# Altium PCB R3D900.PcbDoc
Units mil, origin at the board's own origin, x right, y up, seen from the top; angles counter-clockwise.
Board outline 3947.04 x 3947.04 mil, 2 copper layers (Top Layer, Bottom Layer); 90 components, 62 nets, 371 pads, 65 vias.
Unrouted connection lines stored in the file: 1.
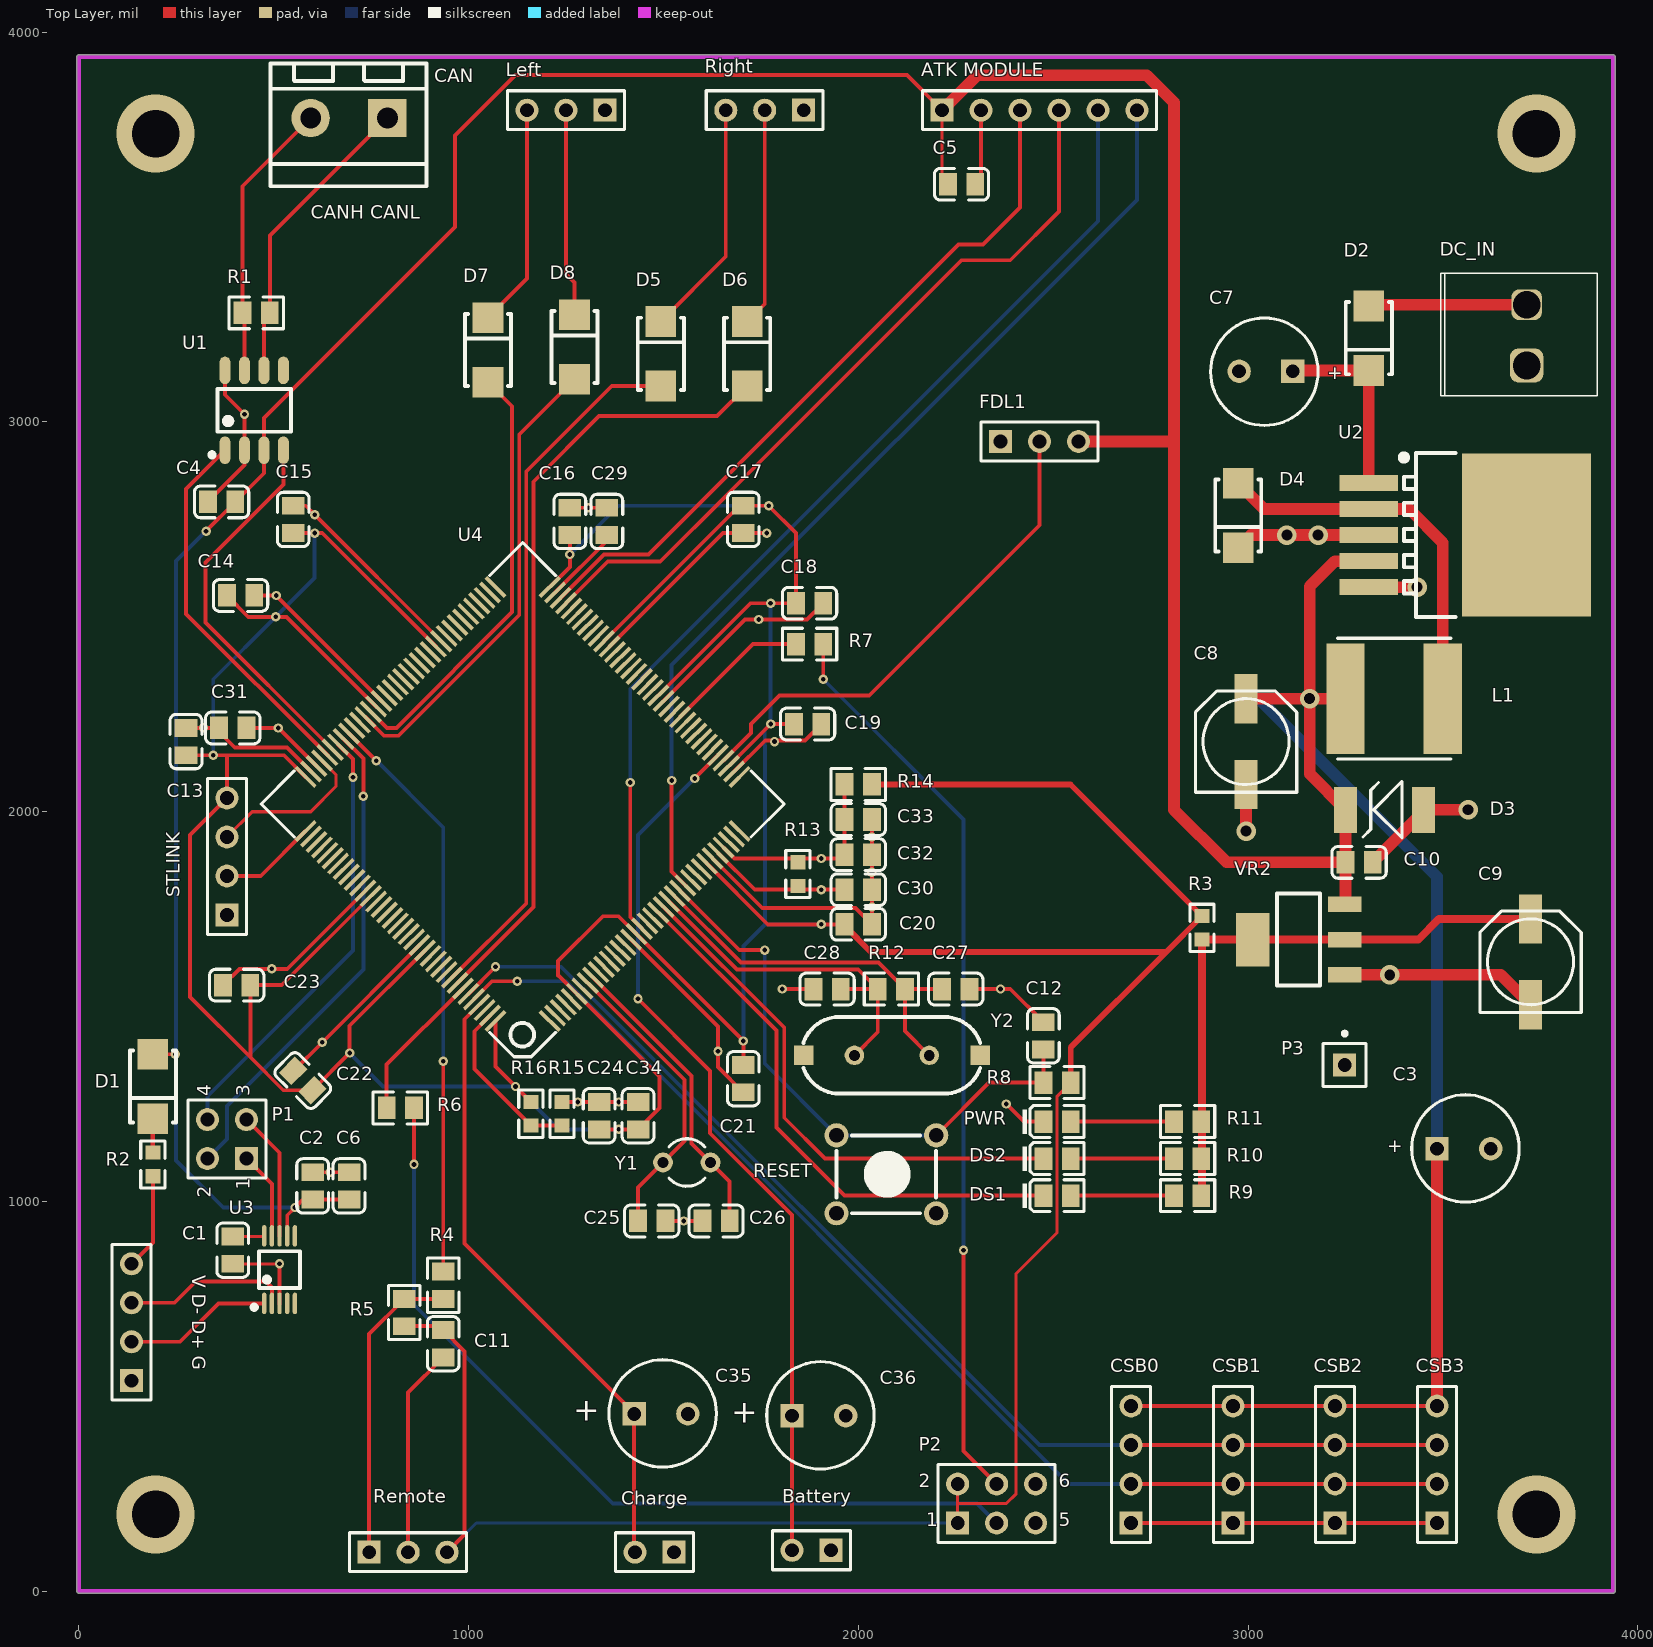
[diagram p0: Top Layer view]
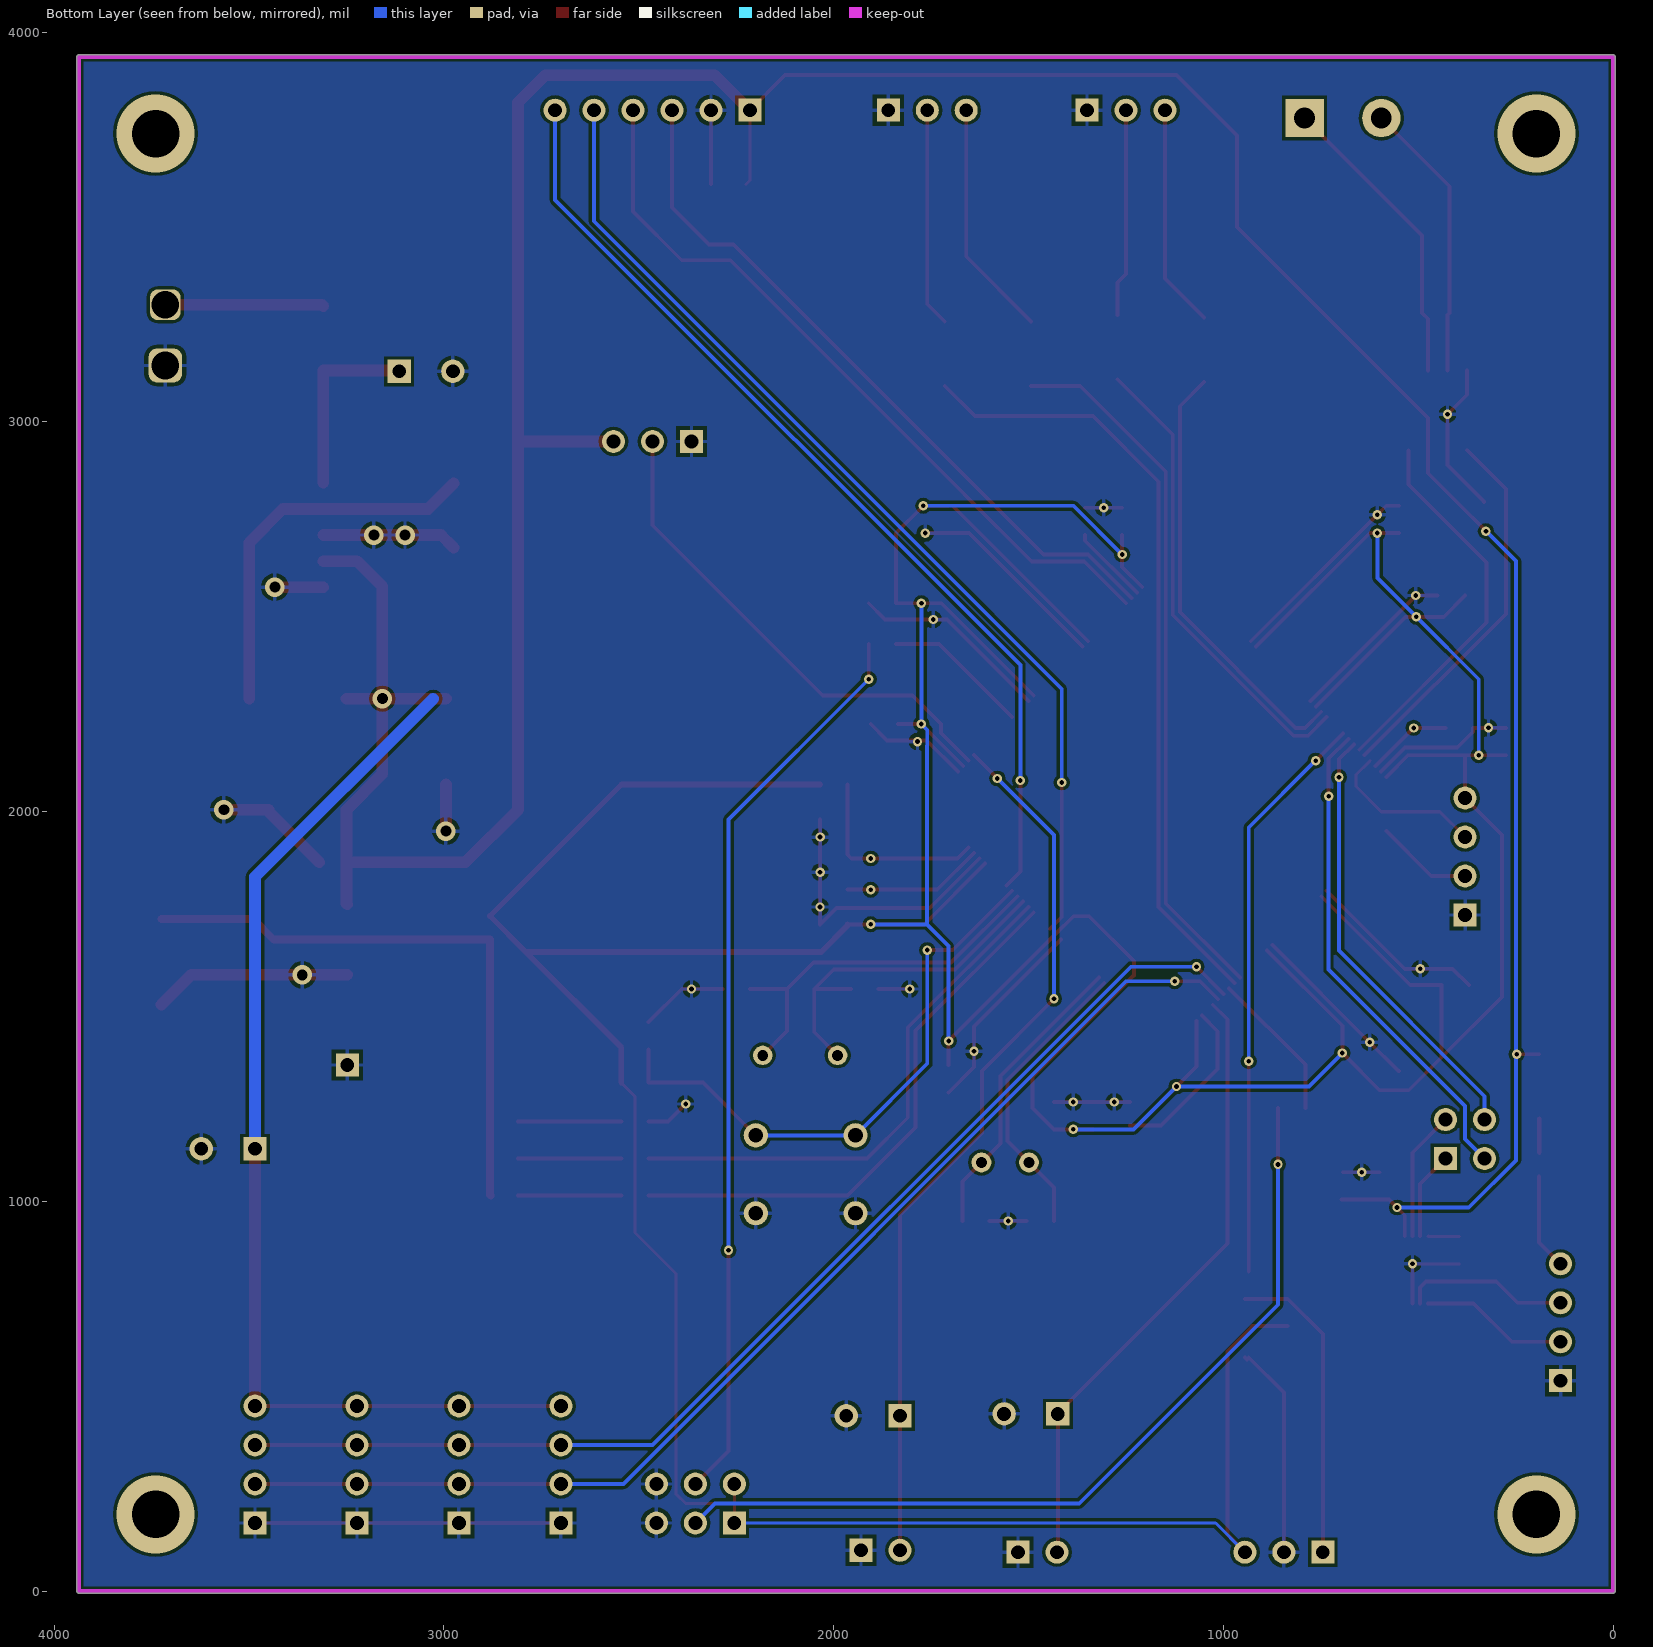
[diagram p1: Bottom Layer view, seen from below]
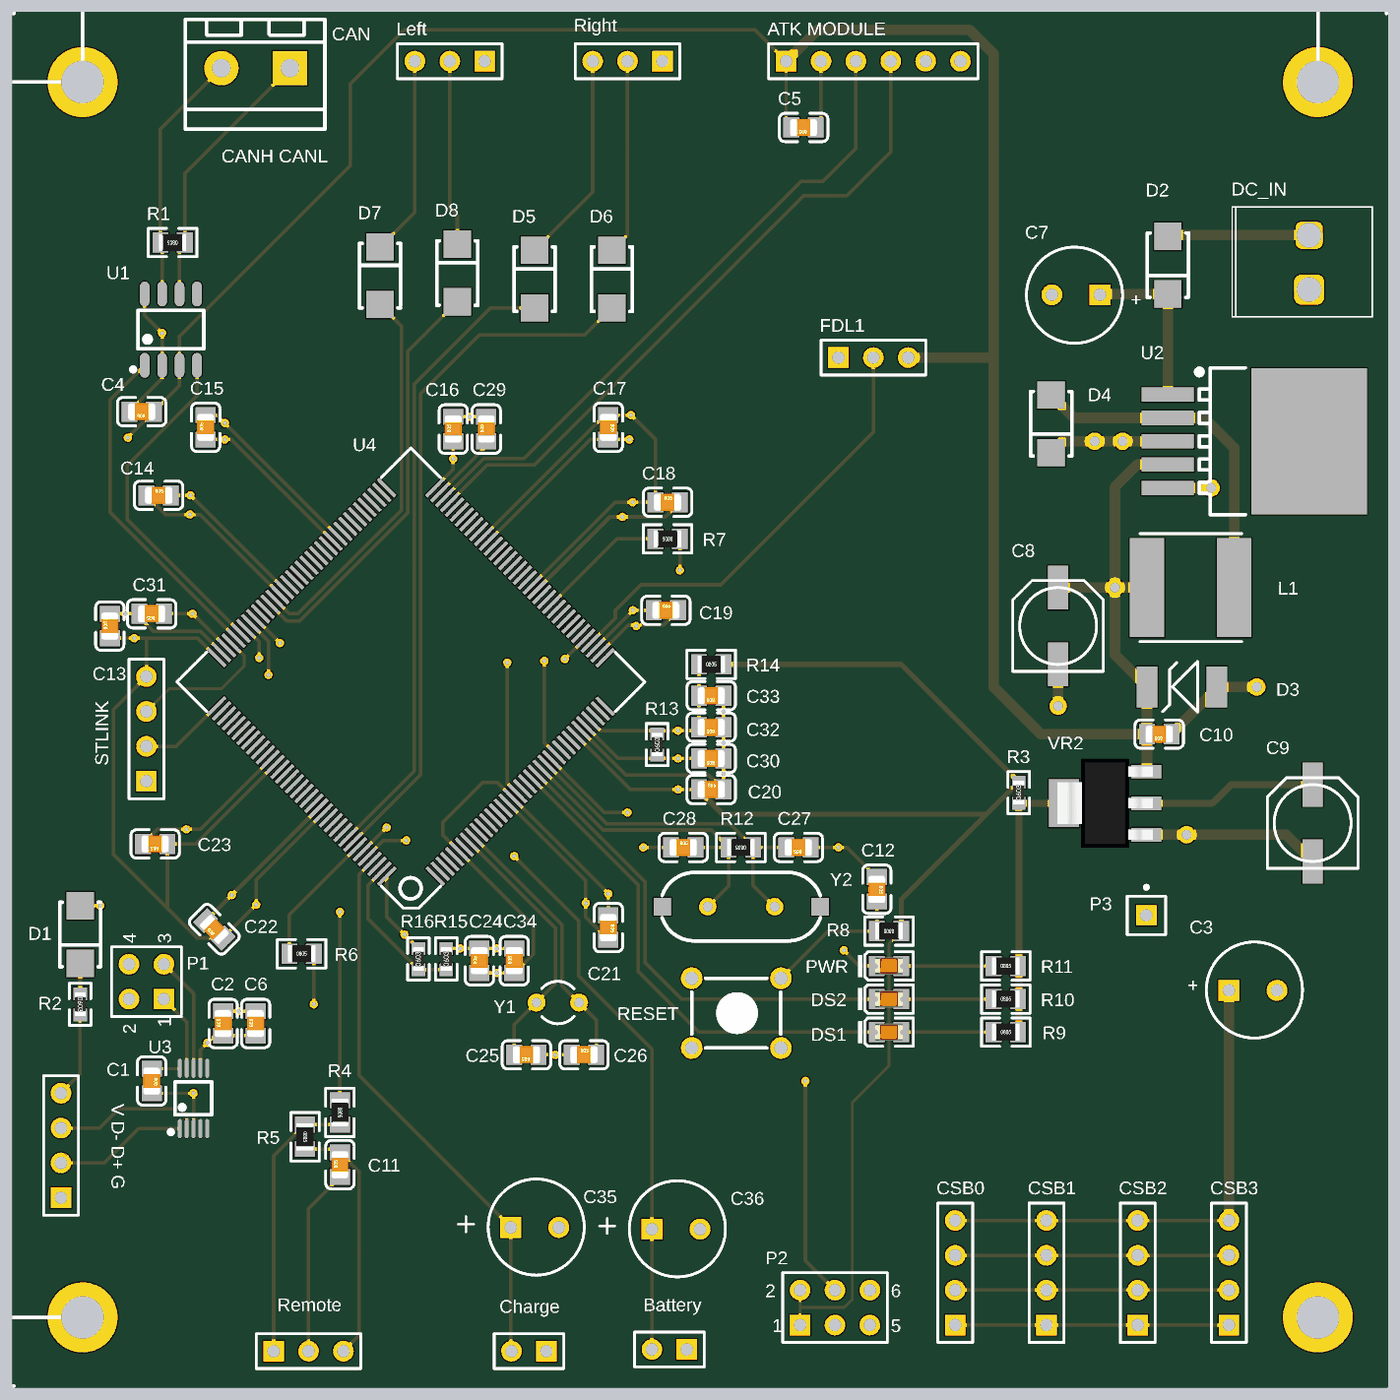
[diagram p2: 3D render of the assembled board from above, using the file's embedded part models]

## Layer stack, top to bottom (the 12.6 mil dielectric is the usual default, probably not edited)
Top Solder: solder mask 0.4, Solder Resist, Dk 3.5
Top Layer: signal copper 1.4
Dielectric 1: dielectric 12.6, FR-4, Dk 4.8
Bottom Layer: signal copper 1.4
Bottom Solder: solder mask 0.4, Solder Resist, Dk 3.5

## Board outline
-5.02,0 ccw(c0,0) 0,-5.02 3937.01,-5.02 ccw(c3937.01,0) 3942.02,0 3942.02,3937.01 ccw(c3937.01,3937.01) 3937.01,3942.02 0,3942.02 ccw(c0,3937.01) -5.02,3937.01

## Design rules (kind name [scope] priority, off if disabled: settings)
Clearance [All] p1: gap=8 ignorepadtopadclearanceinfootprint=TRUE
PolygonConnect [All] p1: connectstyle=Relief reliefconductorwidth=10 reliefentries=4 polygonreliefangle="90 Angle" airgapwidth=10
RoutingVias [All] p1: holewidth=28 width=50 viastyle="Through Hole" minholewidth=28 minwidth=50 maxholewidth=28 maxwidth=50
SolderMaskExpansion [All] p1: expansion=4
Width [All] p1: maxlimit=30 minlimit=8 preferedwidth=10
30 further rules are at their usual default settings.

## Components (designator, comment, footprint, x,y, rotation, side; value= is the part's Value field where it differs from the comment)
"ATK MODULE" "Header 6" HDR1X6 2215,3800 r0 top
Battery "Header 2" HDR1X2 1930,105 r180 top
C1 "100nF(104) 10% 50V" LC-0805_C 395,875 r270 top
C2 "100nF(104) 10% 50V" LC-0805_C 600,1040 r90 top
C3 "Cap" CAP-DIP-3.5 3485,1135 r180 top
C4 "100nF(104) 10% 50V" LC-0805_C 366.42,2795 r180 top
C5 "100nF(104) 10% 50V" LC-0805_C 2265,3610 r180 top
C6 "10uF (106) 10% 25V" LC-0805_C 693.35,1040 r90 top
C7 "Cap" CAP-DIP-3.5 3115,3130 r0 top
C8 "220uF" CC6.56.5 2995,2180 r270 top
C9 "22uF" CC6.56.5 3725,1615 r270 top
C10 "10uF (106) 10% 25V" LC-0805_C 3285,1870 r180 top
C11 "100nF(104) 10% 50V" LC-0805_C 935,634.96 r90 top
C12 "100nF(104) 10% 50V" LC-0805_C 2474.96,1425 r270 top
C13 "100nF(104) 10% 50V" LC-0805_C 275,2180.04 r90 top
C14 "100nF(104) 10% 50V" LC-0805_C 415,2554.92 r0 top
C15 "100nF(104) 10% 50V" LC-0805_C 550,2750 r90 top
C16 "100nF(104) 10% 50V" LC-0805_C 1260,2745 r90 top
C17 "100nF(104) 10% 50V" LC-0805_C 1705,2750 r270 top
C18 "100nF(104) 10% 50V" LC-0805_C 1875,2535 r0 top
C19 "100nF(104) 10% 50V" LC-0805_C 1870,2225 r0 top
C20 "100nF(104) 10% 50V" LC-0805_C 2000,1711.06 r0 top
C21 "100nF(104) 10% 50V" LC-0805_C 1705,1315 r270 top
C22 "100nF(104) 10% 50V" LC-0805_C 574.78,1310.22 r135 top
C23 "100nF(104) 10% 50V" LC-0805_C 405,1555 r180 top
C24 "100nF(104) 10% 50V" LC-0805_C 1335,1220 r90 top
C25 "1.0pF (010) 0.25pF 50V" LC-0805_C 1469.96,950 r180 top
C26 "1.0pF (010) 0.25pF 50V" LC-0805_C 1635,950 r0 top
C27 "22pF (220) 5% 50V" LC-0805_C 2250,1545 r180 top
C28 "22pF (220) 5% 50V" LC-0805_C 1919.96,1545 r0 top
C29 "2.2uF (225) 20% 50V" LC-0805_C 1355,2745 r90 top
C30 "2.2uF (225) 20% 50V" LC-0805_C 2000,1800 r180 top
C31 "2.2uF (225) 20% 50V" LC-0805_C 395,2215 r180 top
C32 "10uF (106) 10% 25V" LC-0805_C 2000,1890 r180 top
C33 "100nF(104) 10% 50V" LC-0805_C 2000,1980 r180 top
C34 "100nF(104) 10% 50V" LC-0805_C 1435,1220 r90 top
C35 "Cap" CAP-DIP-3.5 1425,455 r180 top
C36 "Cap" CAP-DIP-3.5 1830,450 r180 top
CAN "CAN" HEAD2L-0.8 791.85,3780 r180 top
Charge "Header 2" HDR1X2 1527.2,100 r180 top
CSB0 "Header 4" HDR1X4 2700,175 r90 top
CSB1 "Header 4" HDR1X4 2961.67,175 r90 top
CSB2 "Header 4" HDR1X4 3223.33,175 r90 top
CSB3 "Header 4" HDR1X4 3485,175 r90 top
D1 "SS210" LC-SMA(DO-214AC)_S1 190,1295 r90 top
D2 "SS210" LC-SMA(DO-214AC)_S1 3310,3215 r90 top
D3 "SMBJ5.0A" SMBJ 3355,2005 r180 top
D4 "SS54" LC-SMA(DO-214AC)_S1 2975,2760 r90 top
D5 "SS210" LC-SMA(DO-214AC)_S1 1493.33,3175 r270 top
D6 "SS210" LC-SMA(DO-214AC)_S1 1715,3175 r270 top
D7 "SS210" LC-SMA(DO-214AC)_S1 1050,3185 r270 top
D8 "SS210" LC-SMA(DO-214AC)_S1 1271.67,3192.32 r270 top
DC_IN "Header 2" "VH-2A - Circle Hole" 3715,3145 r90 top
DS1 "红灯 0805" LC-0805_LED_S1 2510,1015 r0 top
DS2 "翠绿 0805" LC-0805_LED_S1 2510,1110 r0 top
FDL1 "Header 3" HDR1X3 2365,2950 r0 top
L1 "33uH" L_SOP74 3250,2290 r0 top
Left "Header 3" HDR1X3 1350,3800 r180 top
P1 "Header 2X2" HDR2X2 430,1110 r90 top
P2 "Header 3X2" HDR2X3 2255,175 r0 top
P3 "Plug" PIN1 3248.11,1350.04 r0 top
PWR "蓝灯 0805" LC-0805_LED_S1 2510,1205 r0 top
R1 "120Ω (1200) ±1%" LC-0805_R 455,3280 r180 top
R2 "1Ω (1R00) ±1%" LC-0603_R 190,1095 r270 top
R3 "0Ω (0R0) ±1%" LC-0603_R 2882.18,1702.18 r90 top
R4 "1KΩ (1001) ±1%" LC-0805_R 935,784.96 r270 top
R5 "4.7KΩ (4701) ±1%" LC-0805_R 835,714.96 r270 top
R6 "10KΩ (1002) ±1%" LC-0805_R 825,1239.88 r0 top
R7 "10KΩ (1002) ±1%" LC-0805_R 1875,2430 r180 top
R8 "10KΩ (1002) ±1%" LC-0805_R 2510,1305 r180 top
R9 "510KΩ (5103) ±1%" LC-0805_R 2845,1015 r0 top
R10 "510KΩ (5103) ±1%" LC-0805_R 2845,1110 r0 top
R11 "510KΩ (5103) ±1%" LC-0805_R 2845,1205 r0 top
R12 "1MΩ (1004) ±1%" LC-0805_R 2085,1545 r180 top
R13 "0Ω (0R0) ±1%" LC-0603_R 1845,1840 r90 top
R14 "10Ω (10R0) ±1%" LC-0805_R 2000,2070 r0 top
R15 "0Ω (0R0) ±1%" LC-0603_R 1240,1225 r90 top
R16 "0Ω (0R0) ±1%" LC-0603_R 1160,1225 r90 top
Remote "Header 3" HDR1X3 745,100 r0 top
RESET "KEY_M" KEY_M 1944.09,1169.69 r0 top
Right "Header 3" HDR1X3 1860,3800 r180 top
STLINK "Header 4" HDR1X4 380,1735 r90 top
U1 "CAN/TJA1050T/CM" LC-SOIC-8_150mil 450,3030 r0 top
U2 "LM2596SX-5.0/NOPB" LC-TO-263-5 3309.49,2710 r180 top
U3 "CH340E" LC-MSOP-10 515,825 r0 top
U4 "STM32F407ZET6" LQFP144 1208.14,1463.34 r135 top
"V D- D+ G" "Header 4" HDR1X4 135,540 r90 top (schematic designator "G D+ D- V")
VR2 "AMS1117-3.3" LC-SOT-223 3130,1671.87 r0 top
Y1 "32.768K" R38 1560,1100 r90 top
Y2 "8MHz" XTAL_US 2182.13,1375 r180 top

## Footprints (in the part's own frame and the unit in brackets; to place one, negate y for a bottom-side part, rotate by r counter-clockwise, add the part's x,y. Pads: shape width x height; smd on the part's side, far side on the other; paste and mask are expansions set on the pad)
CAP-DIP-3.5 [mil]
  rect 60x60 hole 35.43: 1(0,0)
  round 60 hole 35.43: 2(-137.8,0)
  silkscreen extent -211,-139 65,137
CC6.56.5 [mm]
  rect 3.2x1.5 smd: 1(-2.794,0) 2(2.8,0)
  silkscreen extent -3.3,-3.3 3.3,3.3
HDR1X2 [mm] "Connector; Header; 2 Position"
  rect 1.5x1.5 hole 0.9: 1(0,0)
  round 1.5 hole 0.9: 2(2.54,0)
  silkscreen extent -1.27,-1.27 3.81,1.27
HDR1X3 [mm] "Connector; Header; 3 Position"
  rect 1.5x1.5 hole 0.9: 1(0,0)
  round 1.5 hole 0.9: 2(2.54,0) 3(5.08,0)
  silkscreen extent -1.27,-1.27 6.35,1.27
HDR1X4 [mm] "Connector; Header; 4 Position"
  rect 1.5x1.5 hole 0.9: 1(0,0)
  round 1.5 hole 0.9: 2(2.54,0) 3(5.08,0) 4(7.62,0)
  silkscreen extent -1.27,-1.27 8.89,1.27
HDR1X6 [mm] "Connector; Header; 6 Position"
  rect 1.5x1.5 hole 0.9: 1(0,0)
  round 1.5 hole 0.9: 2(2.54,0) 3(5.08,0) 4(7.62,0) 5(10.16,0) 6(12.7,0)
  silkscreen extent -1.27,-1.27 13.97,1.27
HDR2X2 [mm] "Connector; Header; 2x2 Position"
  rect 1.5x1.5 hole 0.9: 1(0,0)
  round 1.5 hole 0.9: 2(0,2.54) 3(2.54,0) 4(2.54,2.54)
  silkscreen extent -1.27,-1.27 3.81,3.81
HDR2X3 [mm] "Connector; Header; 3x2 Position"
  rect 1.5x1.5 hole 0.9: 1(0,0)
  round 1.5 hole 0.9: 2(0,2.54) 3(2.54,0) 4(2.54,2.54) 5(5.08,0) 6(5.08,2.54)
  silkscreen extent -1.27,-1.27 6.35,3.81
HEAD2L-0.8 [mm]
  rect 2.5x2.5 hole 1.35: 1(0,0)
  round 2.5 hole 1.35: 2(5,0)
  silkscreen extent -2.54,-3.56 7.62,4.45
KEY_M [mil]
  round 62 hole 38: 1(0,0) 1(255.91,0) 2(0,-200) 2(255.91,-200)
  silkscreen extent 0,-200 255,0
L_SOP74 [mm]
  rect 2.5x7.2 smd: 1(0,0) 2(6.35,0)
  silkscreen extent -0.51,-3.94 6.89,3.94
LC-0603_R [mm]
  rect 0.93x0.98 smd: 1(-0.77,0) 2(0.77,0)
  silkscreen extent -1.53,-0.79 1.54,0.79, body extent -0.85,-0.4 0.85,0.4, height 0.56
LC-0805_C [mm]
  rect 1.16x1.47 smd: 1(-0.89,0) 2(0.89,0)
  silkscreen extent -1.77,-1.04 1.77,1.04, body extent -1,-0.62 1,0.63, height 0.77
LC-0805_LED_S1 [mm]
  rect 1.16x1.47 smd: A(0.89,0) K(-0.89,0)
  silkscreen extent -2.24,-1.04 1.77,1.03, body extent -1.01,-0.62 1.01,0.62, height 1.1
LC-0805_R [mm]
  rect 1.16x1.47 smd: 1(-0.89,0) 2(0.89,0)
  silkscreen extent -1.77,-1.04 1.77,1.03, body extent -1,-0.62 1,0.63, height 0.49
LC-MSOP-10 [mm]
  oval 0.28x1.4 smd mask+0.051: 1(-1,-2.2) 2(-0.5,-2.2) 3(0,-2.2) 4(0.5,-2.2) 5(1,-2.2) 6(1,2.2) 7(0.5,2.2) 8(0,2.2) 9(-0.5,2.2) 10(-1,2.2)
  silkscreen extent -1.8,-2.6 1.33,1.2
LC-SMA(DO-214AC)_S1 [mm]
  rect 2x2 smd: 1(2.1,0) 2(-2.1,0)
  silkscreen extent -2.35,-1.5 2.35,1.5
LC-SOIC-8_150mil [mm]
  oval 0.7x1.8 smd: 1(-1.905,-2.6) 2(-0.635,-2.6) 3(0.635,-2.6) 4(1.905,-2.6) 5(1.905,2.6) 6(0.635,2.6) 7(-0.635,2.6) 8(-1.905,2.6)
  silkscreen extent -2.9,-3.05 2.4,1.4
LC-SOT-223 [mm]
  rect 2.2x1 smd: 1(3,-2.3) 2(3,0) 3(3,2.3)
  rect 2.2x3.5 smd: 2(-3,0)
  silkscreen extent -1.4,-3 1.4,3, body extent -3.49,-3.24 3.49,3.24, height 1.64
LC-TO-263-5 [mm]
  rect 8.4x10.65 smd: 0(-10.3,0)
  rect 3.8x1.05 smd: 1(0,-3.4) 2(0,-1.7) 3(0,0) 4(0,1.7) 5(0,3.4)
  silkscreen extent -5.65,-5.35 -2.1,5.35
LQFP144 [mil]
  rect 70.87x10 smd: 1(-0.35,0.02) 2(-0.35,-19.66) 3(-0.35,-39.35) 4(-0.35,-59.03) 5(-0.35,-78.72) 6(-0.35,-98.4) 7(-0.35,-118.09) 8(-0.35,-137.77) 9(-0.35,-157.46) 10(-0.35,-177.14) 11(-0.35,-196.83) 12(-0.35,-216.51) 13(-0.35,-236.2) 14(-0.35,-255.88) 15(-0.35,-275.57) 16(-0.35,-295.25) 17(-0.35,-314.94) 18(-0.35,-334.62) 19(-0.35,-354.31) 20(-0.35,-373.99) 21(-0.35,-393.68) 22(-0.35,-413.36) 23(-0.35,-433.05) 24(-0.35,-452.73) 25(-0.35,-472.42) 26(-0.35,-492.1) 27(-0.35,-511.79) 28(-0.35,-531.47) 29(-0.35,-551.16) 30(-0.35,-570.84) 31(-0.35,-590.53) 32(-0.35,-610.21) 33(-0.35,-629.9) 34(-0.35,-649.58) 35(-0.35,-669.27) 36(-0.35,-688.95) 73(885.47,-688.95) 74(885.47,-669.27) 75(885.47,-649.58) 76(885.47,-629.9) 77(885.47,-610.21) 78(885.47,-590.53) 79(885.47,-570.84) 80(885.47,-551.16) 81(885.47,-531.47) 82(885.47,-511.79) 83(885.47,-492.1) 84(885.47,-472.42) 85(885.47,-452.73) 86(885.47,-433.05) 87(885.47,-413.36) 88(885.47,-393.68) 89(885.47,-373.99) 90(885.47,-354.31) 91(885.47,-334.62) 92(885.47,-314.94) 93(885.47,-295.25) 94(885.47,-275.57) 95(885.47,-255.88) 96(885.47,-236.2) 97(885.47,-216.51) 98(885.47,-196.83) 99(885.47,-177.14) 100(885.47,-157.46) 101(885.47,-137.77) 102(885.47,-118.09) 103(885.47,-98.4) 104(885.47,-78.72) 105(885.47,-59.03) 106(885.47,-39.35) 107(885.47,-19.66) 108(885.47,0.02)
  rect 10x70.87 smd: 37(98.07,-787.38) 38(117.76,-787.38) 39(137.44,-787.38) 40(157.13,-787.38) 41(176.81,-787.38) 42(196.5,-787.38) 43(216.18,-787.38) 44(235.87,-787.38) 45(255.55,-787.38) 46(275.24,-787.38) 47(294.92,-787.38) 48(314.61,-787.38) 49(334.29,-787.38) 50(353.98,-787.38) 51(373.66,-787.38) 52(393.35,-787.38) 53(413.03,-787.38) 54(432.72,-787.38) 55(452.4,-787.38) 56(472.09,-787.38) 57(491.77,-787.38) 58(511.46,-787.38) 59(531.14,-787.38) 60(550.83,-787.38) 61(570.51,-787.38) 62(590.2,-787.38) 63(609.88,-787.38) 64(629.57,-787.38) 65(649.25,-787.38) 66(668.94,-787.38) 67(688.62,-787.38) 68(708.31,-787.38) 69(727.99,-787.38) 70(747.68,-787.38) 71(767.36,-787.38) 72(787.05,-787.38) 109(787.05,98.45) 110(767.36,98.45) 111(747.68,98.45) 112(727.99,98.45) 113(708.31,98.45) 114(688.62,98.45) 115(668.94,98.45) 116(649.25,98.45) 117(629.57,98.45) 118(609.88,98.45) 119(590.2,98.45) 120(570.51,98.45) 121(550.83,98.45) 122(531.14,98.45) 123(511.46,98.45) 124(491.77,98.45) 125(472.09,98.45) 126(452.4,98.45) 127(432.72,98.45) 128(413.03,98.45) 129(393.35,98.45) 130(373.66,98.45) 131(353.98,98.45) 132(334.29,98.45) 133(314.61,98.45) 134(294.92,98.45) 135(275.24,98.45) 136(255.55,98.45) 137(235.87,98.45) 138(216.18,98.45) 139(196.5,98.45) 140(176.81,98.45) 141(157.13,98.45) 142(137.44,98.45) 143(117.76,98.45) 144(98.07,98.45)
  silkscreen extent -32,-819 917,130
PIN1 [mm] "Connector; Plug"
  rect 1.5x1.5 hole 0.9: 1(0,0)
  silkscreen extent -1.4,-1.4 1.4,2.17
R38 [mm] "Crystal, Thru-Hole; 2 Leads; Body 3.1 x 8.2 mm (Dia.xH)"
  round 1.3 hole 0.7: 1(0,1.55) 2(0,-1.55)
  silkscreen extent -1.55,-1.19 1.55,1.17
SMBJ [mm]
  rect 1.5x3 smd: 1(-2.413,0) 2(2.667,0)
  silkscreen extent -1.02,-1.85 1.52,1.83
"VH-2A - Circle Hole" [mm] "Header 2 use for Power"
  rrect50% 2.2x2.2 hole 1.8: 1(0,0)
  rrect50% 2x2 hole 1.8: 2(3.96,0)
  silkscreen extent -1.98,-4.6 6.02,5.61
XTAL_US [mil]
  round 50 hole 28: 1(0,0) 2(192.13,0)
  rect 50x50 smd: ""(-130.32,0) ""(322.44,0)
  silkscreen extent -131,-98 323,98

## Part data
"ATK MODULE": "Header, 6-Pin"
Battery Charge: "Header, 2-Pin"
C1 C2 C4 C5 C11 C12 C13 C14 C15 C16 C17 C18 C19 C20 C21 C22 C23 C24 C33 C34: library part "0805 100nF(104) 10% 50V", "贴片电容", Package=0805, SuppliersPartNumber=C49678
C3 C7 C35 C36: library part Cap_DIP, "Cap_DIP"
C6 C10 C32: library part "0805 10uF (106) 10% 25V", "贴片电容", Package=0805, SuppliersPartNumber=C15850
C8 C9: library part CAP
C25 C26: library part "0805 1.0pF (010) 0.25pF 50V", "贴片电容", Package=0805, SuppliersPartNumber=C14971
C27 C28: library part "0805 22pF (220) 5% 50V", "贴片电容", Package=0805, SuppliersPartNumber=C1804
C29 C30 C31: library part "0805 2.2uF (225) 20% 50V", "贴片电容", Package=0805, SuppliersPartNumber=C49217
CAN: library part HEAD2
CSB0 CSB1 CSB2 CSB3 STLINK "V D- D+ G": "Header, 4-Pin"
D1 D2 D5 D6 D7 D8: library part "SMA(DO-214AC) SS210", "二极管", Package=SMA(DO-214AC), SuppliersPartNumber=C14996
D3: library part SMBJ, "TVS"
D4: library part "SMA(DO-214AC) SS54", "二极管", Package=SMA(DO-214AC), SuppliersPartNumber=C22452
DC_IN: "贴片2p座"
DS1: library part "0805 红灯", "发光二极管", Package=0805, SuppliersPartNumber=C2295
DS2: library part "0805 翠绿", "发光二极管", Package=0805, SuppliersPartNumber=C2297
FDL1 Left Remote Right: "Header, 3-Pin"
L1: library part L_SOP
P1: "Header, 2-Pin, Dual row"
P2: "Header, 3-Pin, Dual row"
PWR: library part "0805 蓝灯", "发光二极管", Package=0805, SuppliersPartNumber=C2293
R1: library part "0805 120Ω (1200) 1%", "贴片电阻", Package=0805, SuppliersPartNumber=C17437
R2: library part "0603 1Ω (1R00) 1%", "贴片电阻", Package=0603, SuppliersPartNumber=C22936
R3 R13 R15 R16: library part "0603 0Ω (0R0) 1%", "贴片电阻", Package=0603, SuppliersPartNumber=C21189
R4: library part "0805 1KΩ (1001) 1%", "贴片电阻", Package=0805, SuppliersPartNumber=C17513
R5: library part "0805 4.7KΩ (4701) 1%", "贴片电阻", Package=0805, SuppliersPartNumber=C17673
R6 R7 R8: library part "0805 10KΩ (1002) 1%", "贴片电阻", Package=0805, SuppliersPartNumber=C17414
R9 R10 R11: library part "0805 510KΩ (5103) 1%", "贴片电阻", Package=0805, SuppliersPartNumber=C17733
R12: library part "0805 1MΩ (1004) 1%", "贴片电阻", Package=0805, SuppliersPartNumber=C17514
R14: library part "0805 10Ω (10R0) 1%", "贴片电阻", Package=0805, SuppliersPartNumber=C17415
U1: "CAN", Package=SOIC-8_150mil, SuppliersPartNumber=C6952
U2: "DC-DCоƬ", Package=TO-263-5, SuppliersPartNumber=C10002
U3: "USB", Package=SOIC-16_150mil, SuppliersPartNumber=C14267
VR2: library part "SOT-223 AMS1117-3.3", "低压差线性稳压(LDO)", Package=SOT-223, SuppliersPartNumber=C6186
Y1 Y2: library part XTAL, "Crystal Oscillator"

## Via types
v1: diameter 24, hole 12, Top Layer to Bottom Layer, 54 vias
v2: diameter 50, hole 28, Top Layer to Bottom Layer, 7 vias
v3: diameter 200.79, hole 122.05, Top Layer to Bottom Layer, 4 vias

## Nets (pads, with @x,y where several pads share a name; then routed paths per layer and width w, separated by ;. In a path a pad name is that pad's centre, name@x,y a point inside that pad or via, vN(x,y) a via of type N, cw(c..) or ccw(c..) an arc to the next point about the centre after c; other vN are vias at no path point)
+3.3: C9.1 R3.1 R9.2 R10.2 R11.2 VR2.2 | length 1522.6
  Top Layer w20: R9.2 2882.18,1017.14 R3.1 3011.89,1671.87 3248.11,1671.87 3436.87,1671.87 3490,1725 C9.1
+5: "ATK MODULE.1" C2.1 C3.1 C4.1 C5.2 C6.1 C8.1 C10.2 CSB0.4 CSB1.4 CSB2.4 CSB3.4 D1.1 D3.2 FDL1.3 L1.1 U1.3 U2.4 U3.7 VR2.3 | length 12411
  Top Layer w8: 2215,3800 2215,3619.96 C5.2@2224.96,3610
  Top Layer w10: D1.1 v1(247.68,1377.68) ; v1(326.53,2720) 401.46,2794.92 C4.1 475,2868.54 U1.3 475,3010 965,3500 965,3735 1119.96,3889.96 2125.04,3889.96 2215,3800 ; U3.7 534.69,964.69 v1(554.51,984.51) 574.96,1004.96 C2.1 C6.1 C6.1@697.42,1004.96 ; CSB0.4 CSB1.4 CSB2.4 CSB3.4
  Top Layer w30: 2215,3800 2304.96,3889.96 2740,3889.96 2810,3819.96 2810,2950 ; FDL1.3 2810,2950 ; C8.1 v2(3158.07,2290) ; VR2.3 3250,1764.31 D3.2 3158.07,2096.93 v2(3158.07,2290) ; C10.2 2945,1870 2810,2005 2810,2950 ; L1.1 v2(3158.07,2290) ; U2.4 3223.07,2643.07 3158.07,2578.07 v2(3158.07,2290) ; CSB3.4 C3.1
  Bottom Layer w10: v1(326.53,2720) 249.43,2642.9 249.43,1105.57 370.49,984.51 v1(554.51,984.51)
  Bottom Layer w30: 3028.07,2290 3485,1833.07 C3.1
Battery: Battery.2 C36.1 U4.41 | length 2288.7
  Top Layer w10: v1(1434.92,1520) 1620,1334.92 1620,1175 1830,965 C36.1 Battery.2 ; v1(1580,2085.26) U4.41
  Bottom Layer w10: v1(1434.92,1520) 1434.92,1940.18 v1(1580,2085.26)
BOOT0: R6.1 U4.138 | length 387.8
  Top Layer w10: R6.1 789.96,1350.9 U4.138
BOOT1: R7.2 U4.48 | length 375.2
  Top Layer w10: U4.48 1729.87,2430 R7.2
CAN_H: CAN.2 R1.2 U1.7 | length 722.2
  Top Layer w10: U1.7 425,3274.96 R1.2 419.96,3604.96 CAN.2
CAN_L: CAN.1 R1.1 U1.6 | length 778.9
  Top Layer w10: U1.6 475,3264.96 R1.1 490.04,3478.19 CAN.1
CAN_RX: U1.4 U4.103 | length 986.7
  Top Layer w10: U1.4 525,2839.96 325,2639.96 325,2485.64 U4.103
CAN_TX: U1.1 U4.104 | length 974.2
  Top Layer w10: U1.1 275,2827.64 275,2507.8 U4.104
Charge: C35.1 Charge.2 U4.141 | length 1600.8
  Top Layer w10: U4.141 990,1467.42 990,892.2 C35.1@1426.1,456.1 ; C35.1 1425,102.2 Charge.2
FDL1: FDL1.2 U4.40 | length 1299.8
  Top Layer w10: U4.40 1725,2202.42 1725,2225.4 1797.84,2298.24 2028.24,2298.24 2465,2735 FDL1.2 FDL1.2@2465,2960
GBC_KEY: "ATK MODULE.5" U4.18 | length 2609.8
  Top Layer w10: v1(1415,2075) 1415,1729.71 U4.18
  Bottom Layer w10: v1(1415,2075) 1415,2315.04 2615,3515.04 2615,3800
GBC_LED: "ATK MODULE.6" U4.26 | length 2498
  Top Layer w10: v1(1521.21,2080) 1521.21,1846.21 U4.26
  Bottom Layer w10: v1(1521.21,2080) 1521.21,2376.21 2677.5,3532.5 2715,3570 2715,3800
GBC_RX: "ATK MODULE.4" U4.69 | length 1941.3
  Top Layer w10: U4.69 1357.26,2642 1492,2642 1663.06,2813.06 1663.06,2813.26 2264.8,3415 2390,3415 2515,3540 2515,3800
GBC_TX: "ATK MODULE.3" U4.70 | length 1843.5
  Top Layer w10: U4.70 1347.42,2660 1461.76,2660 2256.76,3455 2320,3455 2415,3550 2415,3800
GND: "ATK MODULE.2" "V D- D+ G.1" Battery.1 C1.2 C2.2 C3.2 C4.2 C5.1 C6.2 C7.2 C8.2 C9.2 C10.1 C11.1 C12.1 C13.2 C14.2 C15.2 C16.2 C17.2 C18.2 C19.2 C20.2 C21.2 C22.2 C23.2 C24.2 C25.1 C26.1 C27.1 C28.1 C29.2 C30.1 C31.2 C32.1 C33.1 C34.2 C35.2 C36.2 Charge.1 CSB0.1 CSB1.1 CSB2.1 CSB3.1 D3.1 D4.2 DC_IN.1 FDL1.1 Left.1 P2.5 P2.6 P3.1 PWR.K R15.2 Remote.2 RESET.2 Right.1 STLINK.1 U1.2 U1.8 U2.3 U2.5 U3.3 U4.16 U4.31 U4.38 U4.51 U4.61 U4.83 U4.94 U4.107 U4.120 U4.130 VR2.1 | length 9269.4
  Top Layer w8: C1.2 v1(515,840)
  Top Layer w10: C13.2 v1(320,2215.08) 359.88,2215.08 359.88,2205.12 400,2165 534.29,2165 U4.107 ; C4.2 331.38,2796.38 425,2890 U1.2 v1(425,3020) 375,3070 U1.8 ; C23.2 369.96,1555.08 411.82,1596.94 v1(495,1596.94) 534.9,1596.94 U4.120 ; C14.2 v1(506.27,2554.92) U4.94 ; v1(515,840) v1(515,840) U3.3 ; C22.2 551.36,1335 v1(624.96,1408.61) U4.130 ; C15.2 582.38,2785.04 v1(605,2762.42) U4.83 ; C2.2 C6.2 ; Remote.2 845,509.92 C11.1 ; C11.1@940,594.92 C11.1@945,599.92 ; R15.2 1240.28,1255.04 v1(1280,1255.04) C24.2 C34.2 ; C16.2 v1(1307.5,2780.04) C29.2 ; U4.61 1652.93,2714.96 C17.2 v1(1765,2714.96) ; U4.16 1640,1449.03 v1(1640,1385) 1640,1344.88 1704.92,1279.96 C21.2 ; U4.51 1709.42,2493.06 v1(1745,2493.06) 1868.18,2493.06 1910.04,2534.92 C18.2 ; C25.1 v1(1552.48,950) C26.1 ; U4.31 1753.61,1753 1993.18,1753 C20.2 ; U4.38 1761.32,2183.06 1863.18,2183.06 1905.04,2224.92 C19.2 ; v1(1805,1545) C28.1 ; C20.2 C20.2 ; C33.1 C32.1 C30.1 v1(2035.04,1755.57) C20.2 ; C27.1 v1(2365,1545) 2390,1545 C12.1 ; C5.1@2315,3610 2315,3800 ; v1(2380,1250) 2425,1205 PWR.K ; CSB0.1 CSB1.1 CSB2.1 CSB3.1
  Top Layer w30: D4.2 3007.68,2710 v2(3100,2710) v2(3180,2710) U2.3 ; v2(2995,1950.26) C8.2 ; VR2.1 v2(3363.68,1581.32) 3648.45,1581.32 C9.2 ; U2.5 v2(3433.86,2576.14) ; C10.1 3450,1999.96 D3.1 v2(3565,2005)
  other v1: 645,1075 1385,1255 2035,1845 2035,1935 1785,2180
I2C_SCL: CSB0.3 CSB1.3 CSB2.3 CSB3.3 U4.139 | length 3022.6
  Top Layer w10: U4.139 v1(1069.18,1602.27) ; CSB0.3 CSB1.3 CSB2.3 CSB3.3
  Bottom Layer w10: v1(1069.18,1602.27) 1237.73,1602.27 2465,375 CSB0.3
I2C_SDA: CSB0.2 CSB1.2 CSB2.2 CSB3.2 U4.140 | length 3025
  Top Layer w10: U4.140 1059.74,1565 v1(1125,1565) ; CSB0.2 CSB1.2 CSB2.2 CSB3.2
  Bottom Layer w10: v1(1125,1565) 1249.54,1565 2539.54,275 CSB0.2
LED0: DS1.K U4.21 | length 1434.5
  Top Layer w10: U4.21 1790,1438.22 1790,1190 1965,1015 DS1.K
LED1: DS2.K U4.22 | length 1377.1
  Top Layer w10: U4.22 1810,1446.06 1810,1214.69 1914.68,1110 DS2.K
Left_1: D7.2 Left.3 | length 573.9
  Top Layer w10: D7.2 1150.13,3367.81 1150.13,3535 1150,3535.13 Left.3
Left_2: D8.2 Left.2 | length 534
  Top Layer w10: Left.2 1250,3475.13 1250.13,3475 1250.13,3379.87 1271.67,3358.33 D8.2
NetC1_1: C1.1 U3.10 | length 81.3
  Top Layer w8: C1.1 474.06,910.04 U3.10
NetC7_1: C7.1 D2.2 U2.1 | length 484.6
  Top Layer w30: C7.1 3117.32,3132.32 D2.2 3309.49,3131.81 U2.1
NetC25_2: C25.2 U4.8 Y1.1 | length 762.6
  Top Layer w10: U4.8 1553.98,1312.34 1553.98,1155 Y1.1 1434.92,1035.94 C25.2
NetC26_2: C26.2 U4.9 Y1.2 | length 769.5
  Top Layer w10: U4.9 1571.98,1322.18 1571.98,1149.05 Y1.2 1670.04,1050.98 C26.2
NetC27_2: C27.2 R12.1 U4.24 Y2.1 | length 980.9
  Top Layer w10: U4.24 1698.74,1613 2052.12,1613 2120.04,1545.08 R12.1 ; Y2.1 2120.04,1437.09 R12.1 ; C27.2 R12.1
NetC28_2: C28.2 R12.2 U4.23 Y2.2 | length 918.1
  Top Layer w10: U4.23 1688.9,1595 1999.96,1595 R12.2 ; C28.2 R12.2 ; Y2.2 2049.96,1434.96 R12.2
NetC29_1: C29.1 U4.71 | length 202.2
  Top Layer w10: U4.71 1355,2695.42 C29.1
NetC31_1: C31.1 U4.106 | length 220.3
  Top Layer w10: C31.1 v1(512.13,2215) U4.106
NetD1_2: D1.2 R2.1 | length 87
  Top Layer w12: R2.1 D1.2
NetD2_1: D2.1 DC_IN.2 | length 406.3
  Top Layer w30: D2.1 3313.23,3300.91 DC_IN.2
NetD4_1: D4.1 L1.2 U2.2 | length 988.2
  Top Layer w30: D4.1 3040.75,2776.93 U2.2 3413.07,2776.93 3500,2690 L1.2
NetD5_1: D5.1 U4.136 | length 1813.5
  Top Layer w10: U4.136 1148,1764.61 1148,2873 1367.32,3092.32 D5.1
NetD6_1: D6.1 U4.137 | length 2017
  Top Layer w10: U4.137 1166.78,1755.55 1166.78,2846.78 1335,3015 1637.68,3015 D6.1
NetD7_1: D7.1 U4.96 | length 1119
  Top Layer w10: U4.96 790.43,2215.08 814.9,2215.08 1112,2512.18 1112,3040.32 D7.1
NetD8_1: D8.1 U4.97 | length 1206.5
  Top Layer w10: U4.97 782.67,2195 820.27,2195 1130,2504.73 1130,2967.98 D8.1
NetDS1_A: DS1.A R9.1 | length 264.9
  Top Layer w10: DS1.A R9.1
NetDS2_A: DS2.A R10.1 | length 264.9
  Top Layer w10: DS2.A R10.1
"NetG D+ D- V_2": "V D- D+ G.2" U3.1 | length 381.4
  Top Layer w10: 135,640 260.04,640 358.43,738.39 U3.1
"NetG D+ D- V_3": "V D- D+ G.3" U3.2 | length 430.7
  Top Layer w10: 135,740 245,740 300,795 480,795 495.31,779.69 U3.2
"NetG D+ D- V_4": "V D- D+ G.4" R2.2 | length 247.5
  Top Layer w10: 135,840 190,895 R2.2
NetP1_1: P1.1 U3.9 | length 225.4
  Top Layer w10: P1.1 495.32,1044.68 U3.9
NetP1_3: P1.3 U3.8 | length 333.6
  Top Layer w10: P1.3 515,1125 U3.8
NetP2_3: P2.3 R6.2 | length 2231.8
  Top Layer w10: v1(860.04,1095.04) R6.2
  Bottom Layer w10: v1(860.04,1095.04) 860,735 1370,225 2305,225 P2.3
NetP2_4: P2.4 R7.1 | length 2339.3
  Top Layer w10: v1(1910.04,2340.04) R7.1 ; v1(2270,875) 2270,360 P2.4
  Bottom Layer w10: v1(1910.04,2340.04) 2270,1980.08 v1(2270,875)
NetPWR_A: PWR.A R11.1 | length 264.9
  Top Layer w10: PWR.A R11.1
NetR4_2: R4.2 R5.1 Remote.1 | length 797.4
  Top Layer w10: Remote.1 745,660.08 834.92,750 R5.1 944.92,750 R4.2@945,749.92
NetR15_1: R15.1 R16.1 U4.143 | length 439
  Top Layer w10: U4.143 1015,1436.74 1015,1339.69 R16.1 R15.1
R1: U4.37
REMOTE_IN: R4.1 U4.100 | length 1481.4
  Top Layer w10: U4.100 v1(762.95,2131.21) ; R4.1 v1(935,1360)
  Bottom Layer w10: v1(762.95,2131.21) 763.79,2131.21 935,1960 v1(935,1360)
RESET: C12.2 R8.2 RESET.1 U4.25 | length 1504
  Top Layer w10: U4.25 1694.58,1645 v1(1760,1645) ; RESET.1@2200,1169.69 2335.31,1305 R8.2 C12.2
  Bottom Layer w10: v1(1760,1645) 1760,1353.78 1944.09,1169.69 RESET.1@2200,1169.69
Right_1: D6.2 Right.2 | length 561
  Top Layer w10: D6.2 1760,3302.68 1760,3545 Right.2
Right_2: D5.2 Right.3 | length 611.4
  Top Layer w10: D5.2 1660,3424.34 1660,3520 Right.3
SWCLK: STLINK.2 U4.109 | length 249.7
  Top Layer w10: STLINK.2 466.74,1835 U4.109
SWDIO: STLINK.3 U4.105 | length 415.1
  Top Layer w8: STLINK.3 445,2000 595,2000 660,2065 660,2094.96 U4.105
T1: U4.36
U_RX: P1.4 U4.102 | length 1133.4
  Top Layer w10: U4.102 703.48,2135 v1(703.48,2088.48)
  Bottom Layer w10: P1.4 330,1270 703.48,1643.48 v1(703.48,2088.48)
U_TX: P1.2 U4.101 | length 1263.5
  Top Layer w10: U4.101 730,2136.32 v1(730,2040)
  Bottom Layer w10: P1.2 380,1160 380,1245 730,1595 v1(730,2040)
VCC3.3M: C11.2 C13.1 C14.1 C15.1 C16.1 C17.1 C18.1 C19.1 C20.1 C21.1 C22.1 C23.1 C24.1 C34.1 P2.1 P2.2 R3.2 R5.2 R8.1 R14.2 R16.2 Remote.3 STLINK.4 U4.6 U4.17 U4.30 U4.39 U4.52 U4.62 U4.72 U4.84 U4.95 U4.108 U4.121 U4.131 U4.144 | length 16302.2
  Top Layer w8: P2.1 2255,225 ; P2.2 2255,225 ; R8.1 2510.2,1270.17 2510.2,920.2 2405,815 2405,250 2380,225 2255,225
  Top Layer w10: C13.1 v1(345,2145) 380,2145 ; C14.1 379.96,2554.84 434.81,2500 v1(505,2500) 533.35,2500 U4.95 ; C15.1 v1(605,2714.96) 624.62,2714.96 U4.84 ; U4.108 526.45,2145 380,2145 ; U4.121 520.81,1555 C23.1 440.04,1369.96 ; R5.2 925.08,679.92 C11.2 935.08,670 990.12,614.96 990.12,145.12 Remote.3 ; U4.131 695.04,1450.85 v1(695.04,1380.93) C22.1 599.5,1285.39 524.61,1285.39 440.04,1369.96 ; U4.144 1069.18,1346.14 v1(1120.32,1295) R16.2 ; U4.72 1260,2628.26 v1(1260,2660) C16.1 ; C24.1 C34.1 1435.08,1184.96 1490,1239.88 1490,1320.64 U4.6 1230.64,1580 1230,1580 1230,1617.03 1344.84,1731.87 1385,1731.87 U4.17 v1(1705,1411.87) C21.1 ; U4.62 C17.1@1695.17,2785.04 ; U4.52 1723.52,2535 v1(1775,2535) C18.1 1839.96,2715.04 v1(1769.96,2785.04) C17.1 ; U4.30 1767.71,1711.06 v1(1905,1711.06) C20.1 ; U4.39 v1(1775.42,2225) C19.1 ; 380,2145 STLINK.4 285,1940 285,1525 440.04,1369.96
  Top Layer w15: C20.1 1964.96,1707.45 2032.09,1640.32 2790,1640.32 ; R14.2 2544.68,2070 R3.2 2790,1640.32 ; R8.1 2545.04,1395.35 2790,1640.32
  Bottom Layer w8: Remote.3 1020,175 P2.1
  Bottom Layer w10: v1(345,2145) 345,2340 v1(505,2500) 605,2600 v1(605,2714.96) ; v1(695.04,1380.93) 780.97,1295 v1(1120.32,1295) 1230.32,1185 v1(1385,1185) ; v1(1260,2660) 1385.04,2785.04 v1(1769.96,2785.04) ; v1(1705,1411.87) 1705,1655 1761.06,1711.06 ; v1(1775,2535) 1775,2225.42 v1(1775.42,2225) 1760,2209.58 1760,2169.64 1761.06,2168.58 1761.06,1711.06 ; v1(1905,1711.06) 1761.06,1711.06
VDDA: C32.2 C33.2 R13.2 R14.1 U4.33 | length 507.1
  Top Layer w10: U4.33 1682.29,1880 v1(1905,1880) 1954.96,1880 C32.2 C33.2 R14.1
VREF+: C30.2 R13.1 U4.32 | length 364.3
  Top Layer w10: U4.32 1734.45,1800 v1(1905,1800) C30.2
pads on no net: U1.5 U2.0 U3.4 U3.5 U3.6 U4.1 U4.2 U4.3 U4.4 U4.5 U4.7 U4.10 U4.11 U4.12 U4.13 U4.14 U4.15 U4.19 U4.20 U4.27 U4.28 U4.29 U4.34 U4.35 U4.42 U4.43 U4.44 U4.45 U4.46 U4.47 U4.49 U4.50 U4.53 U4.54 U4.55 U4.56 U4.57 U4.58 U4.59 U4.60 U4.63 U4.64 U4.65 U4.66 U4.67 U4.68 U4.73 U4.74 U4.75 U4.76 U4.77 U4.78 U4.79 U4.80 U4.81 U4.82 U4.85 U4.86 U4.87 U4.88 U4.89 U4.90 U4.91 U4.92 U4.93 U4.98 U4.99 U4.110 U4.111 U4.112 U4.113 U4.114 U4.115 U4.116 U4.117 U4.118 U4.119 U4.122 U4.123 U4.124 U4.125 U4.126 U4.127 U4.128 U4.129 U4.132 U4.133 U4.134 U4.135 U4.142 Y2.
copper on no net:
  other v3: 196.85,196.85 3740.16,196.85 196.85,3740.16 3740.16,3740.16

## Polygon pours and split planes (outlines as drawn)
GND on Bottom Layer "Bottom Layer-GND" (solid, pour order 0): 0,3937.01 3937.01,3937.01 3937.01,0 0,0

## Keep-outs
Keep-Out Layer:
  lines w10: 0,0 3937.01,0 3937.01,3937.01 0,3937.01 0,0

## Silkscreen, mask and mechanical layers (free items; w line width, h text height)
Top Overlay:
  text "CANH CANL" at 595,3510 h60

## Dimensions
3937.01,3937.01 to 0,3937.01 on Top Overlay
196.85,3740.16 to 3740.16,3740.16 on Top Overlay
196.85,3740.16 to 196.85,196.85 on Top Overlay
0,0 to 0,3937.01 on Top Overlay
